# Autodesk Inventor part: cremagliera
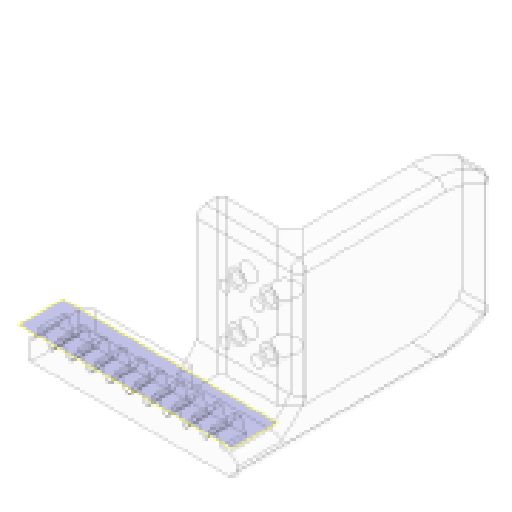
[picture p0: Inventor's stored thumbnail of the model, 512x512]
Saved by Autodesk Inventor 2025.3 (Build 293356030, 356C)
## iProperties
Created: 2025-12
Part Number: cremagliera
Material: Plastica PET
Document SubType Name: Modeling
Designer: R5800u
Density: 1.541 g/cm^3
Appearance: Policarbonato - Trasparente
Author: R5800u
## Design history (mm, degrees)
sketch "Schizzo1"
  geometry: L1 (0, 1.875)-(1.178, 1.875); L2 (0, 0.375)-(1.679, 0.375); L3 (0.632, 3.375)-(1.86, 0); L4 (0.632, 3.375)-(1.178, 3.375); L5 (0, 0)-(0, 5.404); L6 (1.178, 1.875)-(1.178, 3.375); L7 (0, 3.375)-(0.632, 3.375); L8 (0, 1.875)-(-1.178, 1.875); L9 (0, 0.375)-(-1.679, 0.375); L10 (-0.632, 3.375)-(-1.86, 0); L11 (-0.632, 3.375)-(-1.178, 3.375); L12 (-1.178, 1.875)-(-1.178, 3.375); L13 (0, 3.375)-(-0.632, 3.375); L14 (-1.86, 0)-(1.86, 0); L15 (-1.86, 0)-(28.14, 0) reference; L16 (28.14, 0)-(28.14, -5); L17 (28.14, -5)-(-1.86, -5); L18 (-1.86, -5)-(-1.86, 0)
  constraints: 36 end point, 5 horizontal, 5 point on line, 5 symmetric about line, 4 parallel, 2 perpendicular
  dimensions: "d0" = 3.375 distance of L7.start L5.start; "d2" = 1.5 distance between parallel lines of L1 L2; "d3" = 70 deg angle of L3 L4; "d5" = 1.178 distance between parallel lines of L5 L6; "d8" = 30 distance of L16.end L17.end; "d9" = 5 distance of L15.end L16.end
extrude "Estrusione1" new body sketch "Schizzo1" stored distance "d6" = 6; taper "d7" = 0 deg
sketch "Schizzo2"
  geometry: L1 (-1.86, 0)-(1.86, 0) reference; L2 (-1.86, 0)-(45.14, 0) reference; L3 (45.14, 0)-(45.14, -5); L4 (45.14, -5)-(-1.86, -5); L5 (-1.86, -5)-(-1.86, 0); L6 (-1.86, 0)-(-2.86, 0); L7 (-2.86, 0)-(-2.86, -5); L8 (-2.86, -5)-(-1.86, -5); L9 (-1.86, -5)-(-1.86, 0); 3 further points
  constraints: 16 end point, 4 parallel, 3 horizontal, 2 perpendicular
  dimensions: "d10" = 47 distance of L3.end L4.end; "d11" = 5 distance of L2.end L3.end; "d14" = 1 distance of L4.end L7.end
extrude "Estrusione2" join sketch "Schizzo2" stored distance "d12" = 6; taper "d13" = 0 deg
fillet "Raccordo1" dims "d15" = 0.57
pattern_linear "Serie rettangolare1" dims "d18" = 4.71239
sketch "Schizzo3"
  geometry: L1 (-2.86, 1.875)-(45.14, 1.875); L2 (43.044, 3.375)-(41.779, 3.375) reference; 1 further point
  constraints: 2 end point, 1 horizontal
  dimensions: "d19" = 1.5 distance between parallel lines of L2 L1
node "Piano di lavoro1"
node "Piano di lavoro2"
sketch "Schizzo18"
  geometry: L1 (1.724, 0.375)-(0.632, 3.375) reference; L2 (0.632, 3.375)-(-0.632, 3.375) reference; L3 (-0.632, 3.375)-(-1.724, 0.375) reference; L4 (-2.26, 0)-(-2.453, 0) reference; L5 (-2.988, 0.375)-(-4.08, 3.375) reference; L6 (-4.08, 3.375)-(-5.344, 3.375) reference; L7 (-5.344, 3.375)-(-6.436, 0.375) reference; L8 (-6.972, 0)-(-7.165, 0) reference; L9 (-7.701, 0.375)-(-8.793, 3.375) reference; L10 (-8.793, 3.375)-(-10.057, 3.375) reference; L11 (-10.057, 3.375)-(-11.149, 0.375) reference; L12 (-11.684, 0)-(-11.878, 0) reference; L13 (-12.413, 0.375)-(-13.505, 3.375) reference; L14 (-13.505, 3.375)-(-14.769, 3.375) reference; L15 (-14.769, 3.375)-(-15.861, 0.375) reference; L16 (-16.397, 0)-(-16.59, 0) reference; L17 (-17.126, 0.375)-(-18.218, 3.375) reference; L18 (-18.218, 3.375)-(-19.482, 3.375) reference; L19 (-19.482, 3.375)-(-20.573, 0.375) reference; L20 (-21.109, 0)-(-21.302, 0) reference; L21 (-21.838, 0.375)-(-22.93, 3.375) reference; L22 (-22.93, 3.375)-(-24.194, 3.375) reference; L23 (-24.194, 3.375)-(-25.286, 0.375) reference; L24 (-25.822, 0)-(-26.015, 0) reference; L25 (-26.55, 0.375)-(-27.642, 3.375) reference; L26 (-27.642, 3.375)-(-28.906, 3.375) reference; L27 (-28.906, 3.375)-(-29.998, 0.375) reference; L28 (-30.534, 0)-(-30.727, 0) reference; L29 (-31.263, 0.375)-(-32.355, 3.375) reference; L30 (-32.355, 3.375)-(-33.619, 3.375) reference; L31 (-33.619, 3.375)-(-34.711, 0.375) reference; L32 (-35.246, 0)-(-35.44, 0) reference; L33 (-35.975, 0.375)-(-37.067, 3.375) reference; L34 (-37.067, 3.375)-(-38.331, 3.375) reference; L35 (-38.331, 3.375)-(-39.423, 0.375) reference; L36 (-39.959, 0)-(-40.152, 0) reference; L37 (-40.688, 0.375)-(-41.779, 3.375) reference; L38 (-41.779, 3.375)-(-43.044, 3.375) reference; L39 (-43.044, 3.375)-(-44.135, 0.375) reference; L40 (-44.671, 0)-(-45.14, 0) reference; L41 (-45.14, 0)-(-45.14, -5) reference; L42 (-45.14, -5)-(2.86, -5) reference; L43 (2.86, -5)-(2.86, 0) reference; L44 (2.86, 0)-(2.26, 0) reference; L45 (-45.14, -5)-(-23.14, -5); L46 (-23.14, -5)-(-23.14, 0); L47 (-45.14, 0)-(-45.14, -5); A1 r 0.57 centre (-2.26, 0.57) between (-2.26, 0) and (-1.724, 0.375) reference; A2 r 0.57 centre (-2.453, 0.57) between (-2.988, 0.375) and (-2.453, 0) reference; A3 r 0.57 centre (-6.972, 0.57) between (-6.972, 0) and (-6.436, 0.375) reference; A4 r 0.57 centre (-7.165, 0.57) between (-7.701, 0.375) and (-7.165, 0) reference; A5 r 0.57 centre (-11.684, 0.57) between (-11.684, 0) and (-11.149, 0.375) reference; A6 r 0.57 centre (-11.878, 0.57) between (-12.413, 0.375) and (-11.878, 0) reference; A7 r 0.57 centre (-16.397, 0.57) between (-16.397, 0) and (-15.861, 0.375) reference; A8 r 0.57 centre (-16.59, 0.57) between (-17.126, 0.375) and (-16.59, 0) reference; A9 r 0.57 centre (-21.109, 0.57) between (-21.109, 0) and (-20.573, 0.375) reference; A10 r 0.57 centre (-21.302, 0.57) between (-21.838, 0.375) and (-21.302, 0) reference; A11 r 0.57 centre (-25.822, 0.57) between (-25.822, 0) and (-25.286, 0.375) reference; A12 r 0.57 centre (-26.015, 0.57) between (-26.55, 0.375) and (-26.015, 0) reference; A13 r 0.57 centre (-30.534, 0.57) between (-30.534, 0) and (-29.998, 0.375) reference; A14 r 0.57 centre (-30.727, 0.57) between (-31.263, 0.375) and (-30.727, 0) reference; A15 r 0.57 centre (-35.246, 0.57) between (-35.246, 0) and (-34.711, 0.375) reference; A16 r 0.57 centre (-35.44, 0.57) between (-35.975, 0.375) and (-35.44, 0) reference; A17 r 0.57 centre (-39.959, 0.57) between (-39.959, 0) and (-39.423, 0.375) reference; A18 r 0.57 centre (-40.152, 0.57) between (-40.688, 0.375) and (-40.152, 0) reference; A19 r 0.57 centre (-44.671, 0.57) between (-44.671, 0) and (-44.135, 0.375) reference; A20 r 0.57 centre (2.26, 0.57) between (1.724, 0.375) and (2.26, 0) reference; 22 further points
  constraints: 6 end point, 2 horizontal, 1 parallel, 1 perpendicular, 3 other
  dimensions: "d155" = 22 distance of L47.start L46.end; "d160" = 5 distance of L45.end L46.end
  node "Linea chiusa proiettata6"
node "Piano di lavoro4"
extrude "Estrusione11" join sketch "Schizzo18" stored distance "d156" = 6; taper "d157" = 0 deg
sketch "Schizzo19"
  geometry: L1 (0, 5)-(22, 5) reference; L2 (0, 0)-(0, 5) reference; L3 (22, 0)-(0, 0) reference; L4 (22, 5)-(22, 0) reference; L5 (48, 0)-(0, 0) reference; L6 (0, 0)-(22, 0); L7 (22, 0)-(22, 38); L8 (22, 38)-(0, 38); L9 (0, 38)-(0, 0); 3 further points
  constraints: 8 end point, 2 parallel, 1 horizontal, 1 perpendicular
  dimensions: "d171" = 38 distance of L7.end L6.end
extrude "Estrusione12" join sketch "Schizzo19" distance "d158" = 6; taper "d159" = 0 deg
sketch "Schizzo20"
  geometry: L1 (0, 0)-(22, 0) reference; L2 (0, 38)-(8, 38); L3 (8, 38)-(8, 0); L4 (8, 0)-(0, 0); L5 (0, 0)-(0, 38); L6 (0, 38)-(0, 0) reference; L7 (22, 0)-(22, 38) reference; L8 (22, 38)-(0, 38) reference; 2 further points
  constraints: 8 end point, 2 parallel, 2 point on line, 1 horizontal, 1 perpendicular
  dimensions: "d164" = 8 distance of L3.end L4.end
extrude "Estrusione13" join sketch "Schizzo20" distance "d165" = 15; taper "d166" = 0 deg
chamfer "Smusso21" distance "d167" = 5; stored, may be unused: second distance "d168" = 2, angle "d169" = 45 deg
sketch "Schizzo22"
  geometry: L1 (48, -21.1)-(48, 0) reference; L2 (0, 0)-(48, 0) reference; L3 (0, 0)-(0, -6) reference; L4 (26, -6)-(0, -6) reference; L5 (26, -6)-(26, -21.1) reference; L6 (48, -21.1)-(26, -21.1) reference; L7 (0, -6)-(26, -6); L8 (26, -6)-(26, -14); L9 (26, -14)-(0, -14); L10 (0, -14)-(0, -6); 1 further point
  constraints: 8 end point, 2 parallel, 1 horizontal, 1 perpendicular, 1 point on line
  dimensions: "d173" = 8 distance of L7.end L8.end
extrude "Estrusione14" join sketch "Schizzo22" distance "d174" = 5; taper "d175" = 0 deg
fillet "Raccordo3" dims "d176" = 2
sketch "Schizzo24"
  geometry: C1 r 1.2 at (15.25, 12.875) reference; C2 r 1.2 at (7.25, 12.875) reference; C3 r 1.2 at (15.25, 24.875) reference; C4 r 1.2 at (7.25, 24.875) reference; 1 further point
  constraints: 4 centre point, 8 other
hole "Foro7" sketch "Schizzo24" at (15.25, 12.875), (7.25, 12.875), (15.25, 24.875), (7.25, 24.875) diameter "d177" = 2.7; stored, may be unused: countersink angle "d181" = 90 deg, drill point angle "d183" = 118 deg; dims "d178" = 6, "d179" = 4.5, "d180" = 2.9, "d182" = 8
sketch "Schizzo25"
  geometry: L1 (21.1, 38)-(21.1, 0) reference; L2 (10.1, 5)-(0, 5) reference; L3 (0, 0)-(0, 5) reference; L4 (21.1, 0)-(0, 0) reference; L5 (21.1, 38)-(21.1, 0) reference; L6 (15.1, 38)-(21.1, 38) reference; L7 (15.1, 38)-(15.1, 10) reference; L8 (10.1, 5)-(15.1, 10) reference; 3 further points
extrude "Estrusione15" join sketch "Schizzo25" distance "d184" = 3; taper "d185" = 0 deg
sketch "Schizzo26"
  geometry: L1 (22, 0)-(-3, 0) reference; L2 (22, 0)-(22, 38) reference; L3 (22, 38)-(-3, 38) reference; L4 (-3, 0)-(-3, 38) reference; L5 (-3, 38)-(5, 38); L6 (5, 38)-(5, 0); L7 (5, 0)-(-3, 0); L8 (-3, 0)-(-3, 38); C1 r 2.25 at (7.25, 24.875) reference; C2 r 2.25 at (15.25, 24.875) reference; C3 r 2.25 at (7.25, 12.875) reference; C4 r 2.25 at (15.25, 12.875) reference; 2 further points
  constraints: 8 end point, 2 parallel, 1 horizontal, 1 perpendicular, 1 point on line
extrude "Estrusione16" join sketch "Schizzo26" distance "d186" = 30; taper "d187" = 0 deg
sketch "Schizzo27"
  geometry: L1 (51.1, 0)-(51.1, 38) reference; L2 (63.1, 33.731)-(63.1, 4.269); L3 (51.1, 38)-(51.1, 0) reference; A1 r 19 centre (51.1, 19) between (51.1, 0) and (63.1, 33.731); 3 further points
  constraints: 3 point on circle, 2 end point, 2 midpoint, 1 centre point, 1 vertical
  dimensions: "d188" = 12 distance from line of point (51.1, 19) L2
extrude "Estrusione17" join sketch "Schizzo27" stored distance "d189" = 25; taper "d190" = 0 deg
chamfer "Smusso22" distance "d191" = 3; stored, may be unused: second distance "d192" = 2, angle "d193" = 45 deg
fillet "Raccordo4" dims "d194" = 2
fillet "Raccordo5" dims "d195" = 2
chamfer "Smusso23" distance "d196" = 1; stored, may be unused: second distance "d197" = 2, angle "d198" = 45 deg
node "Solido1"
node "Linea chiusa proiettata7"
node "Linea chiusa proiettata8"
node "Linea chiusa proiettata10"
node "Linea chiusa proiettata11"
node "Linea chiusa proiettata12"
other parameters: "d1" = 1.5, "d20" = 0
